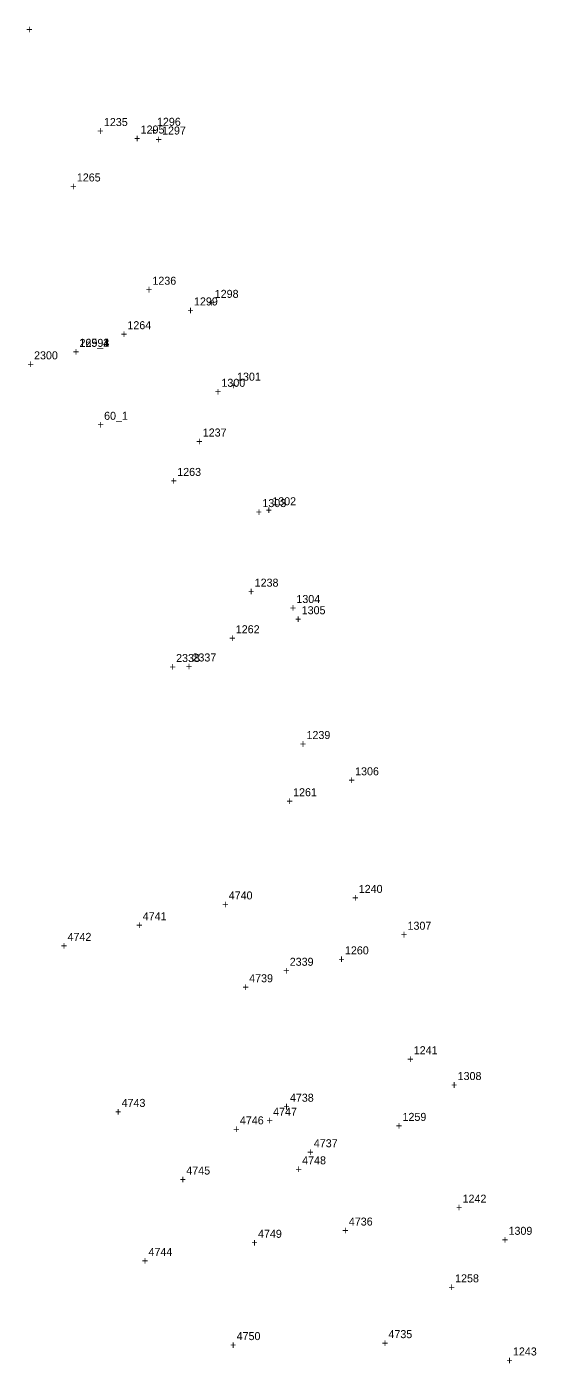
# Model space of a CAD drawing. Extents: x 1036751 to 1042192, y 772604 to 785439.
# Drawn here: x 1037623.4 to 1037782.6, y 780962.6 to 781380 of the extents above; entities that cross this region are included whole.
import ezdxf

# ---------------------------------------------------------------- set-up
doc = ezdxf.new("R2010")
doc.units = 0
for name, color, linetype in [('S_Control_Geodetic_ControlPoint', 7, 'Continuous'), ('S_Control_Temp_Traverse', 7, 'Continuous'), ('S_Ground_Elevation', 7, 'Continuous'), ('S_Roadway_Centerline', 7, 'Continuous'), ('S_Roadway_Edge_Pavement', 7, 'Continuous'), ('S_Roadway_Edge_TW', 7, 'Continuous'), ('S_Traffic_Sign_DoublePost', 7, 'Continuous'), ('S_Utilities_GuyWire3', 7, 'Continuous'), ('S_Utilities_Pole_Power', 7, 'Continuous')]:
    doc.layers.add(name, color=color, linetype=linetype)

msp = doc.modelspace()

# ---------------------------------------------------------------- texts
at = {"layer": 'S_Control_Geodetic_ControlPoint'}
for s, p in [('60', (1037647.55, 781257.27)), ('60', (1037647.55, 781257.27)), ('60', (1037647.55, 781257.27)), ('60', (1037647.55, 781257.27)), ('60_1', (1037647.55, 781257.27)), ('+', (1037645.49, 781254.52)), ('+', (1037645.49, 781254.52)), ('+', (1037645.49, 781254.52)), ('+', (1037645.49, 781254.52)), ('+', (1037645.49, 781254.52))]:
    msp.add_text(s, height=2.5, dxfattribs=at).set_placement(p)
at = {"layer": 'S_Control_Temp_Traverse'}
for s, p in [('165', (1037639.84, 781280.08)), ('165_1', (1037639.84, 781280.08)), ('165_3', (1037639.84, 781280.08)), ('165_2', (1037639.84, 781280.08)), ('165_4', (1037639.84, 781280.08)), ('+', (1037637.78, 781277.33)), ('+', (1037637.78, 781277.33)), ('+', (1037637.78, 781277.33)), ('+', (1037637.78, 781277.33)), ('+', (1037637.78, 781277.33))]:
    msp.add_text(s, height=2.5, dxfattribs=at).set_placement(p)
at = {"layer": 'S_Ground_Elevation'}
for s, p in [('4740', (1037686.48, 781107.48)), ('+', (1037684.42, 781104.73)), ('+', (1037657.55, 781098.23)), ('4741', (1037659.61, 781100.98)), ('4742', (1037636.13, 781094.54)), ('+', (1037634.07, 781091.79)), ('4739', (1037692.87, 781081.62)), ('+', (1037690.81, 781078.87)), ('4738', (1037705.6, 781044.31)), ('+', (1037650.95, 781039.94)), ('4743', (1037653.01, 781042.69)), ('4747', (1037700.35, 781039.96)), ('+', (1037703.54, 781041.56)), ('4746', (1037689.97, 781037.24)), ('+', (1037698.29, 781037.21)), ('+', (1037687.91, 781034.49)), ('+', (1037711.01, 781027.35)), ('4737', (1037713.07, 781030.1)), ('4748', (1037709.43, 781024.76)), ('+', (1037671.16, 781018.83)), ('4745', (1037673.23, 781021.58)), ('+', (1037707.37, 781022.01)), ('4749', (1037695.63, 781001.82)), ('+', (1037721.95, 781002.89)), ('4736', (1037724.01, 781005.64)), ('+', (1037693.57, 780999.07)), ('4744', (1037661.42, 780996.17)), ('+', (1037659.36, 780993.42)), ('4750', (1037688.95, 780969.87)), ('4735', (1037736.38, 780970.48)), ('+', (1037686.89, 780967.12)), ('+', (1037734.32, 780967.73))]:
    msp.add_text(s, height=2.5, dxfattribs=at).set_placement(p)
at = {"layer": 'S_Roadway_Centerline'}
for s, p in [('1235', (1037647.49, 781349)), ('+', (1037645.42, 781346.25)), ('1236', (1037662.64, 781299.45)), ('+', (1037660.58, 781296.7)), ('1237', (1037678.37, 781252.05)), ('+', (1037676.31, 781249.3)), ('+', (1037692.53, 781202.4)), ('1238', (1037694.59, 781205.15)), ('1239', (1037710.78, 781157.57)), ('+', (1037708.72, 781154.82)), ('+', (1037725.04, 781106.77)), ('1240', (1037727.1, 781109.52)), ('+', (1037742.23, 781056.4)), ('1241', (1037744.29, 781059.15)), ('1242', (1037759.54, 781012.78)), ('+', (1037757.48, 781010.03)), ('1243', (1037775.28, 780965.07)), ('+', (1037773.22, 780962.32))]:
    msp.add_text(s, height=2.5, dxfattribs=at).set_placement(p)
at = {"layer": 'S_Roadway_Edge_Pavement'}
for s, p in [('+', (1037623.21, 781377.92)), ('1296', (1037664.06, 781349.08)), ('+', (1037662, 781346.33)), ('1297', (1037665.66, 781346.36)), ('+', (1037663.6, 781343.61)), ('1265', (1037639.03, 781331.7)), ('+', (1037636.97, 781328.95)), ('1298', (1037682.11, 781295.35)), ('+', (1037680.05, 781292.6)), ('1264', (1037654.82, 781285.56)), ('+', (1037652.76, 781282.81)), ('1301', (1037689.08, 781269.48)), ('+', (1037687.02, 781266.73)), ('1263', (1037670.4, 781239.74)), ('+', (1037668.34, 781236.99)), ('+', (1037698.03, 781227.83)), ('1302', (1037700.09, 781230.58)), ('1305', (1037709.28, 781196.55)), ('1262', (1037688.69, 781190.61)), ('+', (1037707.21, 781193.8)), ('+', (1037686.63, 781187.86)), ('1306', (1037725.97, 781146.25)), ('1261', (1037706.59, 781139.71)), ('+', (1037723.91, 781143.5)), ('+', (1037704.53, 781136.96)), ('1307', (1037742.34, 781098.02)), ('+', (1037740.28, 781095.27)), ('1260', (1037722.79, 781090.33)), ('+', (1037720.73, 781087.58)), ('+', (1037755.94, 781048.33)), ('1308', (1037758, 781051.08)), ('+', (1037738.71, 781035.58)), ('1259', (1037740.78, 781038.33)), ('1309', (1037773.9, 781002.75)), ('+', (1037771.84, 781000)), ('1258', (1037757.21, 780987.91)), ('+', (1037755.15, 780985.16))]:
    msp.add_text(s, height=2.5, dxfattribs=at).set_placement(p)
at = {"layer": 'S_Roadway_Edge_TW'}
for s, p in [('1295', (1037658.96, 781346.67)), ('+', (1037656.89, 781343.92)), ('+', (1037673.57, 781290.23)), ('1299', (1037675.63, 781292.98)), ('1300', (1037684.2, 781267.57)), ('+', (1037682.14, 781264.82)), ('1303', (1037696.99, 781230.01)), ('+', (1037694.93, 781227.26)), ('1304', (1037707.62, 781200.05)), ('+', (1037705.56, 781197.3))]:
    msp.add_text(s, height=2.5, dxfattribs=at).set_placement(p)
at = {"layer": 'S_Traffic_Sign_DoublePost'}
for s, p in [('2338', (1037670.04, 781181.63)), ('2337', (1037675.15, 781181.8)), ('+', (1037667.98, 781178.88)), ('+', (1037673.09, 781179.05))]:
    msp.add_text(s, height=2.5, dxfattribs=at).set_placement(p)
at = {"layer": 'S_Utilities_GuyWire3'}
for s, p in [('+', (1037623.61, 781273.4)), ('2300', (1037625.67, 781276.15))]:
    msp.add_text(s, height=2.5, dxfattribs=at).set_placement(p)
at = {"layer": 'S_Utilities_Pole_Power'}
for s, p in [('2299', (1037639.88, 781280.04)), ('+', (1037637.82, 781277.29)), ('2339', (1037705.54, 781086.77)), ('+', (1037703.48, 781084.02))]:
    msp.add_text(s, height=2.5, dxfattribs=at).set_placement(p)

doc.saveas('drawing.dxf')
